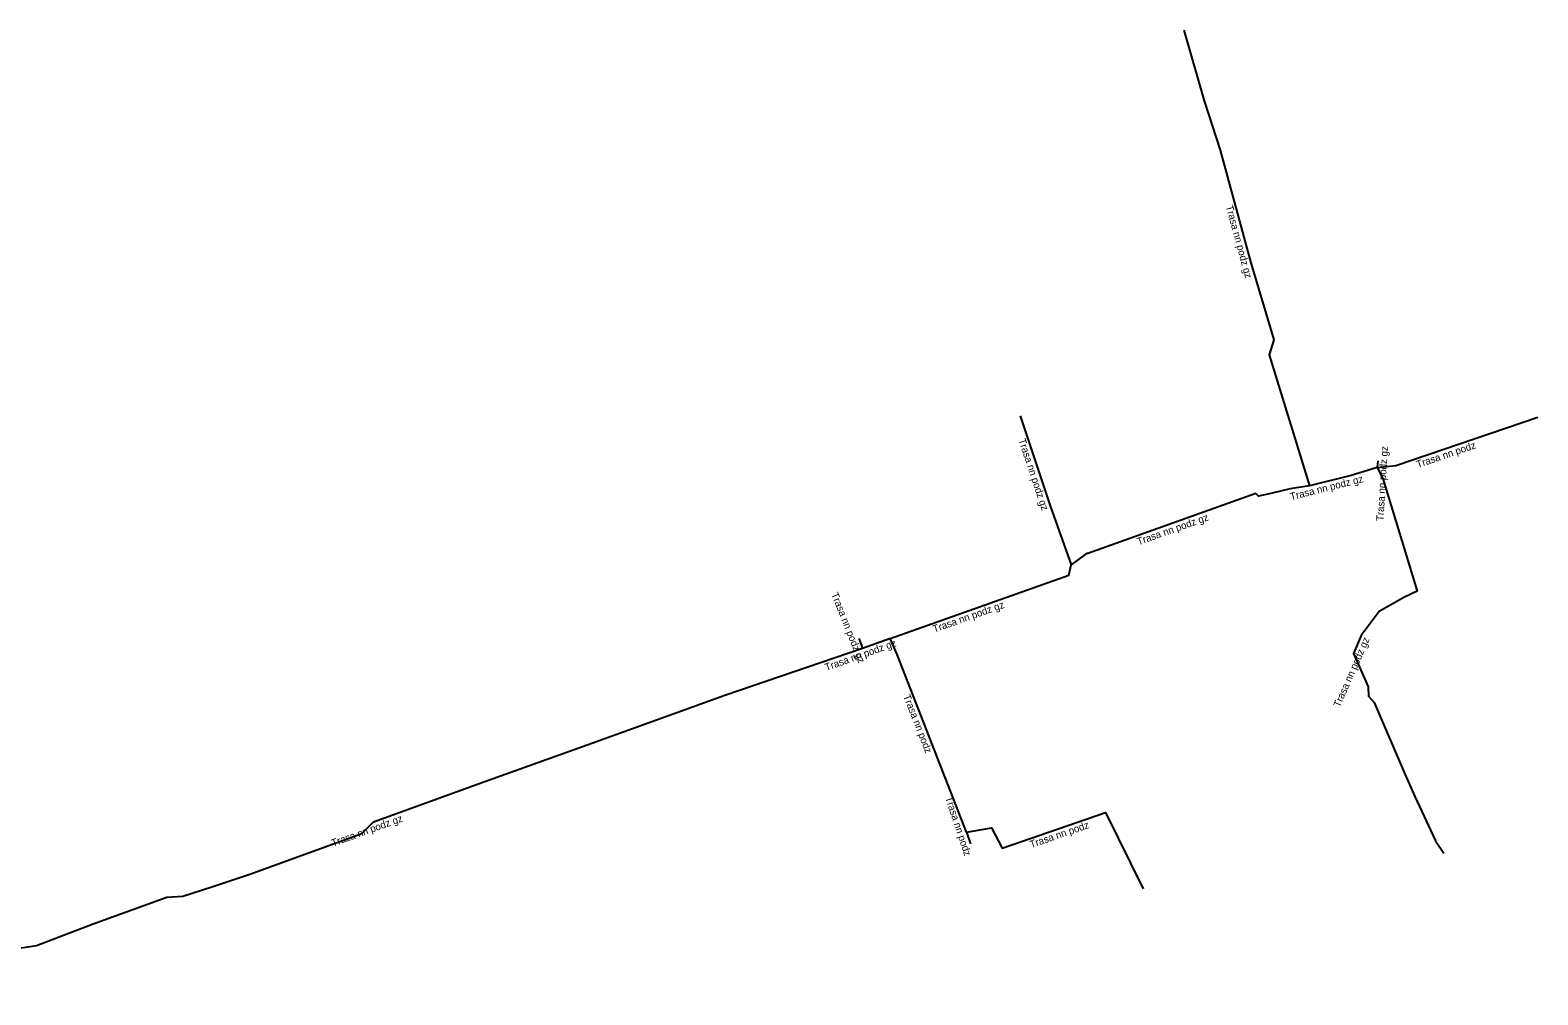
# Model space of a CAD drawing. Extents: x -703044 to -702068, y -1022301 to -1021908.
# Drawn here: x -702935.6 to -702831.7, y -1021974.1 to -1021907.6 of the extents above; entities that cross this region are included whole.
import ezdxf

# ---------------------------------------------------------------- set-up
doc = ezdxf.new("R2010")
doc.units = 0
doc.layers.add('Popiskový text - Ostatní atributy Trasy', color=7, linetype='Continuous')
doc.layers.add('Spojnice NN', color=7, linetype='Continuous')

msp = doc.modelspace()

# ---------------------------------------------------------------- linework, layer by layer
at = {"layer": 'Spojnice NN'}
for points in [[(-702856.08, -1021907.62), (-702854.67, -1021912.48), (-702853.56, -1021915.89), (-702851.45, -1021923.65), (-702849.87, -1021928.95), (-702850.18, -1021929.98), (-702847.41, -1021939.02)], [(-702867.34, -1021934.19), (-702865.28, -1021940.4), (-702863.83, -1021944.46)], [(-702842.74, -1021937.75), (-702841.46, -1021937.61), (-702831.68, -1021934.29)], [(-702842.74, -1021937.75), (-702844.55, -1021938.3), (-702847.41, -1021939.02)], [(-702842.74, -1021937.75), (-702842.37, -1021938.51), (-702839.99, -1021946.26), (-702840.91, -1021946.7), (-702842.6, -1021947.67), (-702843.85, -1021949.33), (-702844.39, -1021950.56), (-702843.38, -1021952.85), (-702843.34, -1021953.5), (-702842.96, -1021953.95), (-702840.87, -1021958.81), (-702840.15, -1021960.42), (-702838.73, -1021963.47), (-702838.16, -1021964.32)], [(-702842.71, -1021937.29), (-702842.74, -1021937.75)], [(-702847.41, -1021939.02), (-702848.75, -1021939.22), (-702850.08, -1021939.53), (-702850.92, -1021939.73), (-702851.1, -1021939.54), (-702862.69, -1021943.67), (-702862.78, -1021943.67), (-702863.83, -1021944.46)], [(-702876.29, -1021949.52), (-702863.99, -1021945.16), (-702863.83, -1021944.46)], [(-702943.94, -1021974.08), (-702941.45, -1021973.27), (-702939.31, -1021972.32), (-702936.46, -1021970.88), (-702935.11, -1021970.67), (-702931.21, -1021969.19), (-702926.13, -1021967.34), (-702925.03, -1021967.29), (-702923.04, -1021966.64), (-702920.41, -1021965.77), (-702912.7, -1021962.97), (-702911.89, -1021962.17), (-702904.3, -1021959.41), (-702896.85, -1021956.74), (-702887.69, -1021953.43), (-702878.2, -1021950.19)], [(-702878.47, -1021949.52), (-702878.2, -1021950.19)], [(-702878.2, -1021950.19), (-702876.35, -1021949.54), (-702876.29, -1021949.52)], [(-702871.04, -1021962.88), (-702875.83, -1021950.64), (-702876.29, -1021949.52)], [(-702871.04, -1021962.88), (-702869.31, -1021962.58), (-702868.58, -1021963.97), (-702861.46, -1021961.51), (-702858.87, -1021966.77)], [(-702871.04, -1021962.88), (-702870.77, -1021963.68)]]:
    msp.add_lwpolyline(points, dxfattribs=at)

# ---------------------------------------------------------------- texts
at = {"layer": 'Popiskový text - Ostatní atributy Trasy'}
for s, rotation, p in [('Trasa nn podz gz', 285.2114, (-702853.18, -1021919.76)), ('Trasa nn podz gz', 288.3519, (-702867.47, -1021935.85)), ('Trasa nn podz gz', 86.447, (-702842.32, -1021941.45)), ('Trasa nn podz', 18.7945, (-702839.95, -1021937.79)), ('Trasa nn podz gz', 14.1305, (-702848.68, -1021940.01)), ('Trasa nn podz gz', 19.6131, (-702859.19, -1021943.11)), ('Trasa nn podz gz', 291.6096, (-702880.37, -1021946.47)), ('Trasa nn podz gz', 19.4928, (-702873.26, -1021949.13)), ('Trasa nn podz gz', 19.4943, (-702880.7, -1021951.77)), ('Trasa nn podz gz', 66.2974, (-702845.33, -1021954.31)), ('Trasa nn podz', 291.3588, (-702875.41, -1021953.5)), ('Trasa nn podz', 288.4134, (-702872.52, -1021960.5)), ('Trasa nn podz gz', 19.9831, (-702914.69, -1021963.88)), ('Trasa nn podz', 19.0603, (-702866.59, -1021963.97))]:
    msp.add_text(s, height=0.5, rotation=rotation, dxfattribs=at).set_placement(p)

doc.saveas('drawing.dxf')
